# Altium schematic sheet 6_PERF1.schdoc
size 426 x 302 mm; Symbol: Sheet_A3_Whycan; Device: Sheet_A3; @Project Name: Avaota A1 八核 AIoT 开发板; @Update Date: 2024-04-03; @Page No: 8; @Page Count: 13
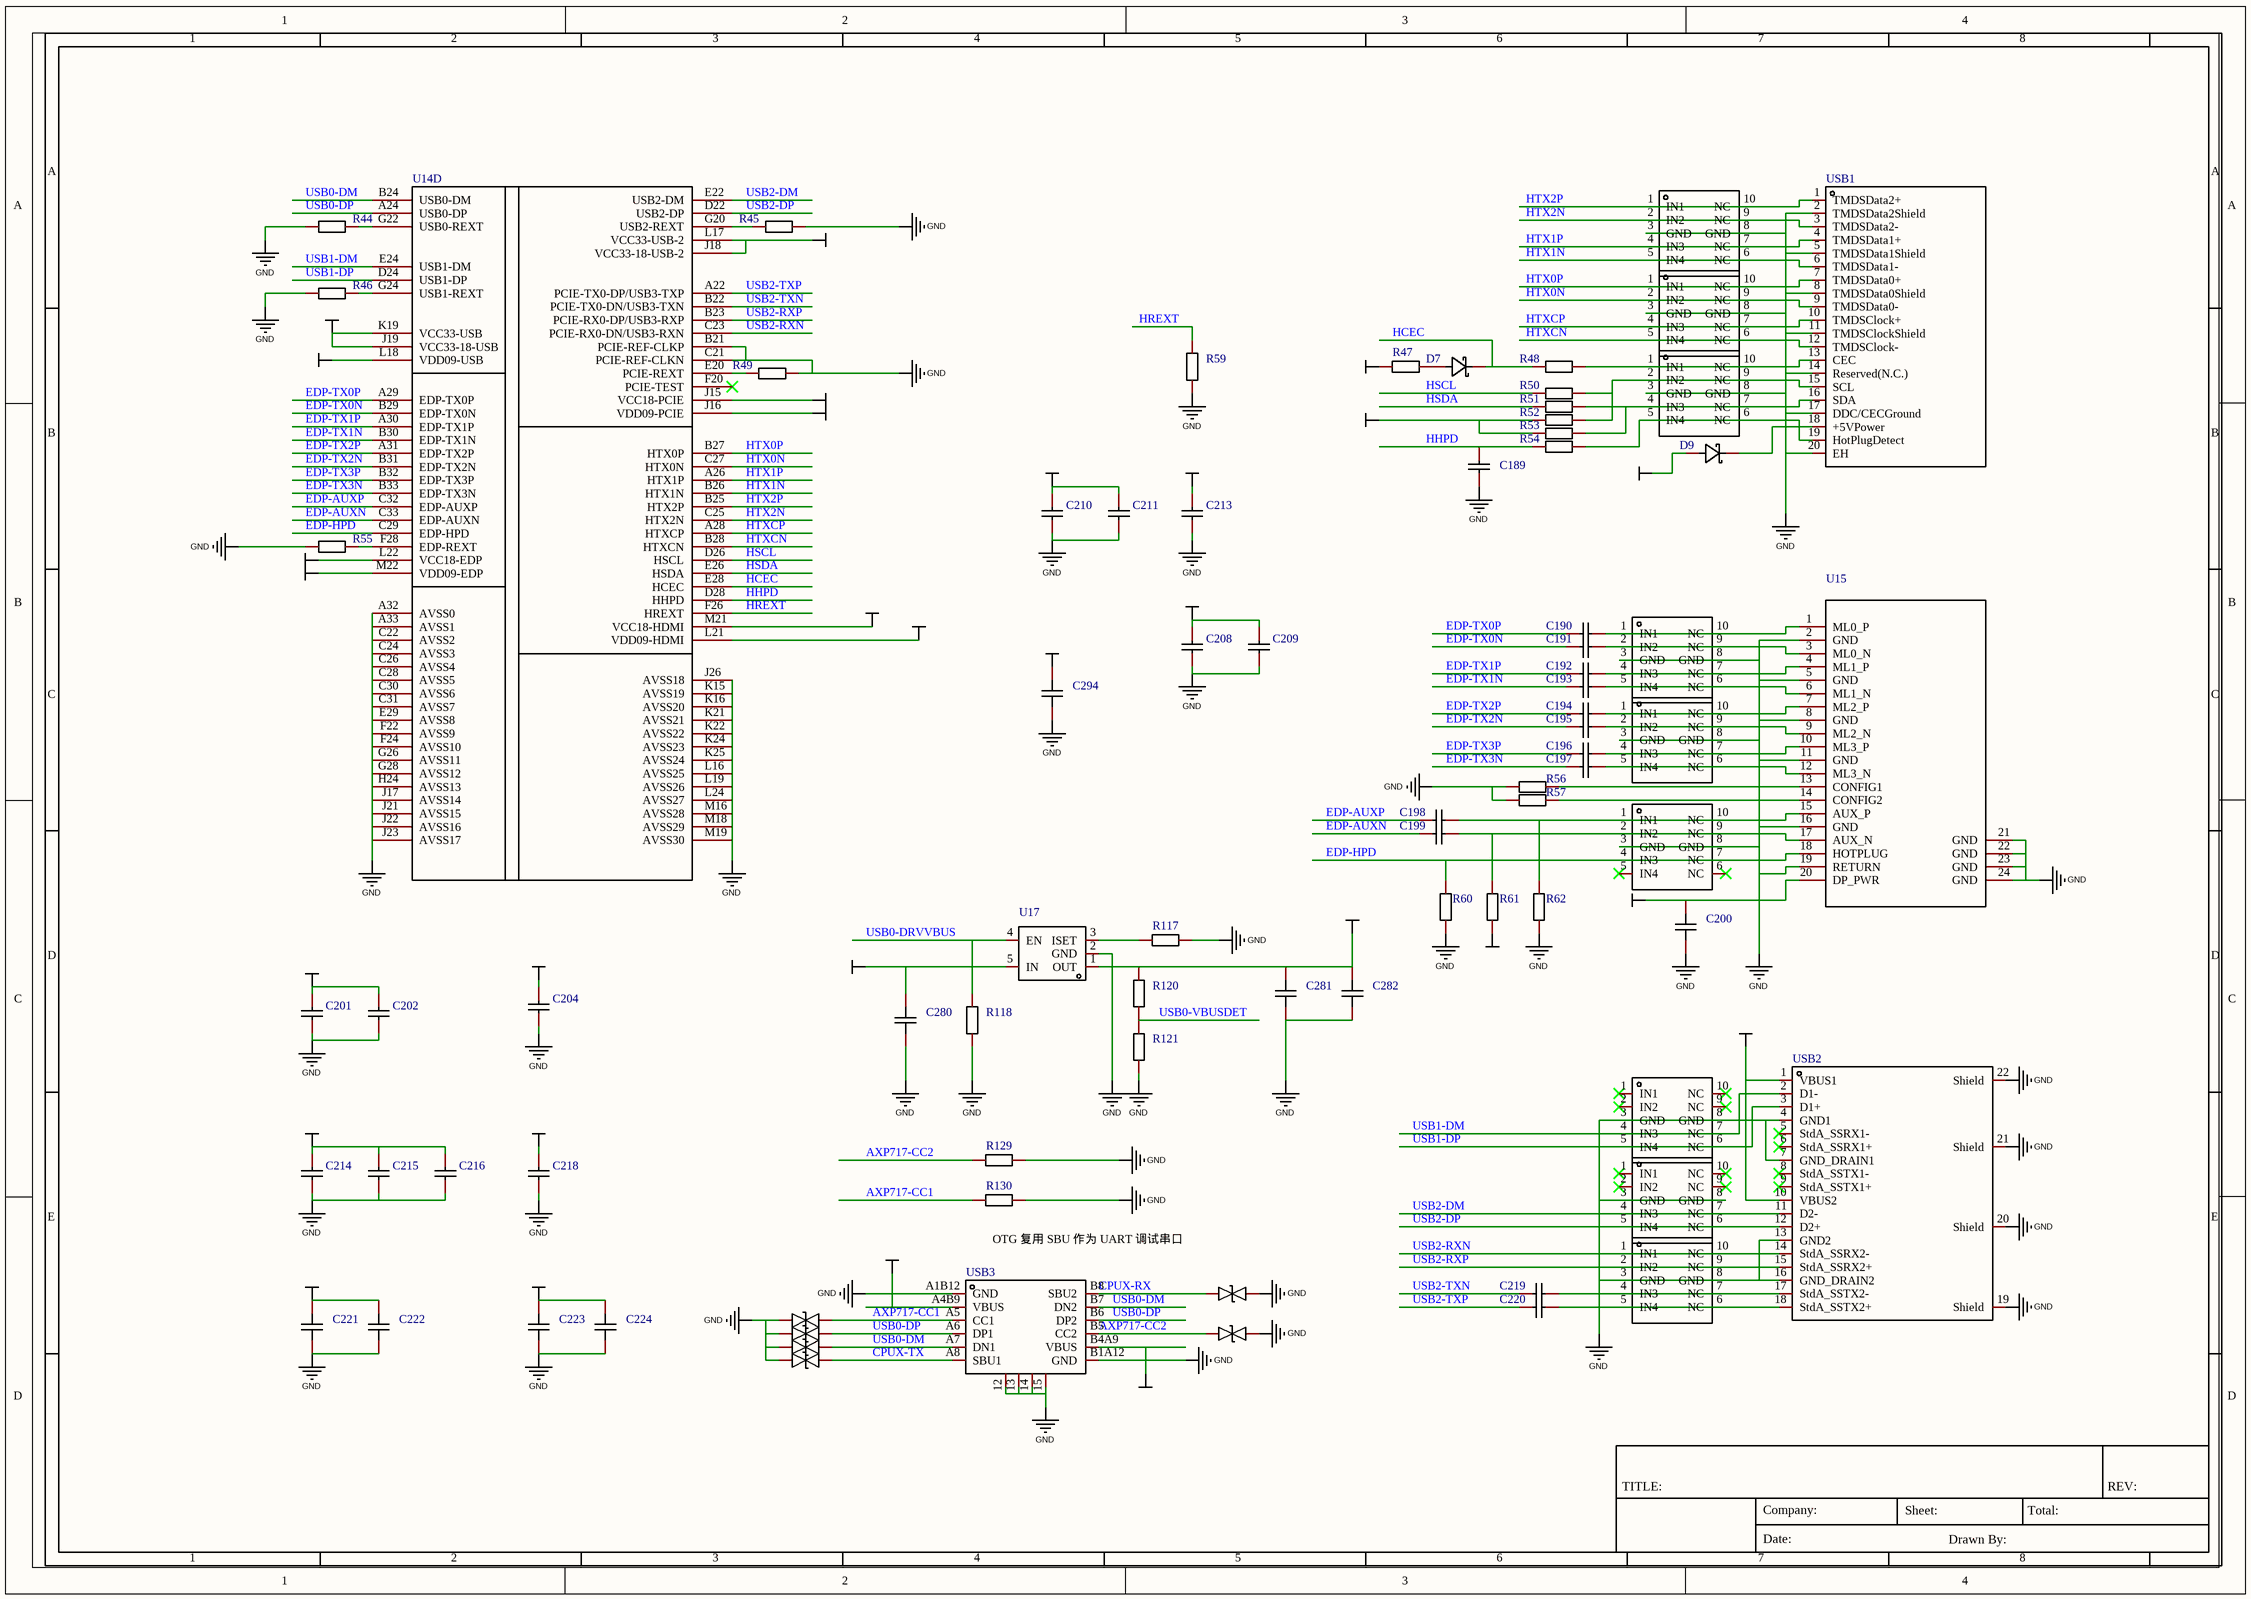
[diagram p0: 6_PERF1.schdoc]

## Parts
C189  GRM033R61A104KE15D  [c0201 nsk]  (value not drawn)
C190  GRM033R61A104KE15D  [c0201 nsk]  (value not drawn)
C191  GRM033R61A104KE15D  [c0201 nsk]  (value not drawn)
C192  GRM033R61A104KE15D  [c0201 nsk]  (value not drawn)
C193  GRM033R61A104KE15D  [c0201 nsk]  (value not drawn)
C194  GRM033R61A104KE15D  [c0201 nsk]  (value not drawn)
C195  GRM033R61A104KE15D  [c0201 nsk]  (value not drawn)
C196  GRM033R61A104KE15D  [c0201 nsk]  (value not drawn)
C197  GRM033R61A104KE15D  [c0201 nsk]  (value not drawn)
C198  GRM033R61A104KE15D  [c0201 nsk]  (value not drawn)
C199  GRM033R61A104KE15D  [c0201 nsk]  (value not drawn)
C200  CAP_0402  [c0402-nsk]  (value not drawn)
C201  GRM033R61A104KE15D  [c0201 nsk]  (value not drawn)
C202  GRM033R61A104KE15D  [c0201 nsk]  (value not drawn)
C204  GRM033R61A104KE15D  [c0201 nsk]  (value not drawn)
C208  GRM033R61A104KE15D  [c0201 nsk]  (value not drawn)
C209  GRM033R61A104KE15D  [c0201 nsk]  (value not drawn)
C210  GRM033R61A104KE15D  [c0201 nsk]  (value not drawn)
C211  GRM033R61A104KE15D  [c0201 nsk]  (value not drawn)
C213  GRM033R61A104KE15D  [c0201 nsk]  (value not drawn)
C214  GRM033R61A104KE15D  [c0201 nsk]  (value not drawn)
C215  GRM033R61A104KE15D  [c0201 nsk]  (value not drawn)
C216  GRM033R61A104KE15D  [c0201 nsk]  (value not drawn)
C218  GRM033R61A104KE15D  [c0201 nsk]  (value not drawn)
C219  GRM033R61A104KE15D  [c0201 nsk]  (value not drawn)
C220  GRM033R61A104KE15D  [c0201 nsk]  (value not drawn)
C221  CAP_0402  [c0402-nsk]  (value not drawn)
C222  CAP_0402  [c0402-nsk]  (value not drawn)
C223  CAP_0402  [c0402-nsk]  (value not drawn)
C224  CAP_0402  [c0402-nsk]  (value not drawn)
C280  CAP_0402  [c0402-nsk]  (value not drawn)
C281  CAP_0603  [C0603-NSK]  (value not drawn)
C282  CAP_0603  [C0603-NSK]  (value not drawn)
C294  CAP_1206  [C1206]  (value not drawn)
D5  RClamp0524PATCT_C40960  [SLP2510P8_L2.5-W1.0-P0.50-BL]  (value not drawn)
D6  RClamp0524PATCT_C40960  [SLP2510P8_L2.5-W1.0-P0.50-BL]  (value not drawn)
D7  B5819WT_C2997265  [SOD-523_L1.2-W0.8-LS1.6-RD-1 NSK]  (value not drawn)
D8  RClamp0524PATCT_C40960  [SLP2510P8_L2.5-W1.0-P0.50-BL]  (value not drawn)
D9  B5819WT_C2997265  [SOD-523_L1.2-W0.8-LS1.6-RD-1 NSK]  (value not drawn)
D10  RClamp0524PATCT_C40960  [SLP2510P8_L2.5-W1.0-P0.50-BL]  (value not drawn)
D11  RClamp0524PATCT_C40960  [SLP2510P8_L2.5-W1.0-P0.50-BL]  (value not drawn)
D12  RClamp0524PATCT_C40960  [SLP2510P8_L2.5-W1.0-P0.50-BL]  (value not drawn)
D13  RClamp0524PATCT_C40960  [SLP2510P8_L2.5-W1.0-P0.50-BL]  (value not drawn)
D14  RClamp0524PATCT_C40960  [SLP2510P8_L2.5-W1.0-P0.50-BL]  (value not drawn)
D15  RClamp0524PATCT_C40960  [SLP2510P8_L2.5-W1.0-P0.50-BL]  (value not drawn)
D24  0402ESDA-05N  [d0402]  (value not drawn)
D25  0402ESDA-05N  [d0402]  (value not drawn)
D26  0402ESDA-05N  [d0402]  (value not drawn)
D27  0402ESDA-05N  [d0402]  (value not drawn)
D30  0402ESDA-05N  [d0402]  (value not drawn)
D31  0402ESDA-05N  [d0402]  (value not drawn)
R44  Res_0201  [r0201 nsk]  (value not drawn)
R45  Res_0201  [r0201 nsk]  (value not drawn)
R46  Res_0201  [r0201 nsk]  (value not drawn)
R47  Res_0201  [r0201 nsk]  (value not drawn)
R48  Res_0201  [r0201 nsk]  (value not drawn)
R49  Res_0201  [r0201 nsk]  (value not drawn)
R50  Res_0201  [r0201 nsk]  (value not drawn)
R51  Res_0201  [r0201 nsk]  (value not drawn)
R52  Res_0201  [r0201 nsk]  (value not drawn)
R53  Res_0201  [r0201 nsk]  (value not drawn)
R54  Res_0201  [r0201 nsk]  (value not drawn)
R55  Res_0201  [r0201 nsk]  (value not drawn)
R56  Res_0201  [r0201 nsk]  (value not drawn)
R57  Res_0201  [r0201 nsk]  (value not drawn)
R59  Res_0201  [r0201 nsk]  (value not drawn)
R60  Res_0201  [r0201 nsk]  (value not drawn)
R61  Res_0201  [r0201 nsk]  (value not drawn)
R62  Res_0201  [r0201 nsk]  (value not drawn)
R117  Res_0201  [r0201 nsk]  (value not drawn)
R118  Res_0201  [r0201 nsk]  (value not drawn)
R120  Res_0201  [r0201 nsk]  (value not drawn)
R121  Res_0201  [r0201 nsk]  (value not drawn)
R129  Res_0201  [r0201 nsk]  (value not drawn)
R130  Res_0201  [r0201 nsk]  (value not drawn)
U14  T527  [T527-BGA664]  (value not drawn)  (part D of 8)
U15  DP_TH_SIDE_VERTICAL  [DP_TH_SIDE_VERTICAL]  (value not drawn)
U17  SY6280AAC_C55136  [SOT-23-5_L3.0-W1.7-P0.95-LS2.8-BL]  (value not drawn)
USB1  HDMI-001C_C2836126  [HDMI-SMD_HDMI-001C]  (value not drawn)
USB2  USB-303WSD-BRY  [USB-A-TH_XUNPU_USB-303WSD-BRY]  (value not drawn)
USB3  TYPEC-304-BCP16  [USB-C-SMD_TYPEC-304-BCP16-1]  (value not drawn)

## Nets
GND: C189.1 C200.1 C201.1 C202.1 C204.1 C208.1 C209.1 C210.1 C211.1 C213.1 C214.1 C215.1 C216.1 C218.1 C221.1 C222.1 C223.1 C224.1 C280.1 C281.1 C282.1 C294.1 D5.3(GND) D5.8(GND) D6.3(GND) D6.8(GND) D8.3(GND) D8.8(GND) D10.3(GND) D10.8(GND) D11.3(GND) D11.8(GND) D12.3(GND) D12.8(GND) D13.3(GND) D13.8(GND) D14.3(GND) D14.8(GND) D15.3(GND) D15.8(GND) D24.1 D25.1 D26.1 D27.1 D30.1 D31.1 R44.1 R45.2 R46.1 R49.1 R55.1 R56.1 R57.1 R59.1 R60.1 R62.1 R117.2 R118.1 R121.1 R129.1 R130.1 U14.A32(AVSS0) U14.A33(AVSS1) U14.B21(PCIE-REF-CLKP) U14.C21(PCIE-REF-CLKN) U14.C22(AVSS2) U14.C24(AVSS3) U14.C26(AVSS4) U14.C28(AVSS5) U14.C30(AVSS6) U14.C31(AVSS7) U14.E29(AVSS8) U14.F22(AVSS9) U14.F24(AVSS10) U14.G26(AVSS11) U14.G28(AVSS12) U14.H24(AVSS13) U14.J17(AVSS14) U14.J21(AVSS15) U14.J22(AVSS16) U14.J23(AVSS17) U14.J26(AVSS18) U14.K15(AVSS19) U14.K16(AVSS20) U14.K21(AVSS21) U14.K22(AVSS22) U14.K24(AVSS23) U14.K25(AVSS24) U14.L16(AVSS25) U14.L19(AVSS26) U14.L24(AVSS27) U14.M16(AVSS28) U14.M18(AVSS29) U14.M19(AVSS30) U15.2(GND) U15.5(GND) U15.8(GND) U15.11(GND) U15.16(GND) U15.19(RETURN) U15.21(GND) U15.22(GND) U15.23(GND) U15.24(GND) U17.2(GND) USB1.2(TMDSData2Shield) USB1.5(TMDSData1Shield) USB1.8(TMDSData0Shield) USB1.11(TMDSClockShield) USB1.14(Reserved(N.C.)) USB1.17(DDC/CECGround) USB1.20(EH) USB2.4(GND1) USB2.7(GND_DRAIN1) USB2.13(GND2) USB2.16(GND_DRAIN2) USB2.19(Shield) USB2.20(Shield) USB2.21(Shield) USB2.22(Shield) USB3.12 USB3.13 USB3.14 USB3.15 USB3.A1B12(GND) USB3.B1A12(GND)
VBUS: C221.2 C222.2 C280.2 C294.2 D9.2(A) R52.1 R53.1 U17.5(IN) USB2.1(VBUS1) USB2.10(VBUS2)
VBUS-USB: C281.2 C282.2 R120.2 U17.1(OUT) USB3.A4B9(VBUS) USB3.B4A9(VBUS)
VCC18-EDP: U14.L22(VCC18-EDP)
VCC18-HDMI: C201.2 C202.2 U14.M21(VCC18-HDMI)
VCC18-PCIE: C208.2 C209.2 U14.J15(VCC18-PCIE)
VCC33-USB: C204.2 U14.J18(VCC33-18-USB-2) U14.J19(VCC33-18-USB) U14.K19(VCC33-USB) U14.L17(VCC33-USB-2)
VCC-3V3: C200.2 C223.2 C224.2 R61.1 U15.20(DP_PWR)
VCC-IO: R47.1
VDD09-EDP: C213.2 U14.M22(VDD09-EDP)
VDD09-HDMI: C214.2 C215.2 C216.2 U14.L21(VDD09-HDMI)
VDD09-PCIE: C210.2 C211.2 U14.J16(VDD09-PCIE)
VDD09-USB: C218.2 U14.L18(VDD09-USB)
AXP717-CC1: D24.2 R130.2 USB3.A5(CC1)
AXP717-CC2: D31.2 R129.2 USB3.B5(CC2)
CPUX-RX: D30.2 USB3.B8(SBU2)
CPUX-TX: D27.2 USB3.A8(SBU1)
EDP-AUXN: C199.1 U14.C33(EDP-AUXN)
EDP-AUXP: C198.1 U14.C32(EDP-AUXP)
EDP-HPD: D12.4(IN3) D12.7(NC) R60.2 U14.C29(EDP-HPD) U15.18(HOTPLUG)
EDP-TX0N: C191.1 U14.B29(EDP-TX0N)
EDP-TX0P: C190.1 U14.A29(EDP-TX0P)
EDP-TX1N: C193.1 U14.B30(EDP-TX1N)
EDP-TX1P: C192.1 U14.A30(EDP-TX1P)
EDP-TX2N: C195.1 U14.B31(EDP-TX2N)
EDP-TX2P: C194.1 U14.A31(EDP-TX2P)
EDP-TX3N: C197.1 U14.B33(EDP-TX3N)
EDP-TX3P: C196.1 U14.B32(EDP-TX3P)
HCEC: D7.1(K) R48.1 U14.E28(HCEC)
HHPD: C189.2 R54.1 U14.D28(HHPD)
HREXT: R59.2 U14.F26(HREXT)
HSCL: R50.1 U14.D26(HSCL)
HSDA: R51.1 U14.E26(HSDA)
HTX0N: D6.2(IN2) D6.9(NC) U14.C27(HTX0N) USB1.9(TMDSData0-)
HTX0P: D6.1(IN1) D6.10(NC) U14.B27(HTX0P) USB1.7(TMDSData0+)
HTX1N: D5.5(IN4) D5.6(NC) U14.B26(HTX1N) USB1.6(TMDSData1-)
HTX1P: D5.4(IN3) D5.7(NC) U14.A26(HTX1P) USB1.4(TMDSData1+)
HTX2N: D5.2(IN2) D5.9(NC) U14.C25(HTX2N) USB1.3(TMDSData2-)
HTX2P: D5.1(IN1) D5.10(NC) U14.B25(HTX2P) USB1.1(TMDSData2+)
HTXCN: D6.5(IN4) D6.6(NC) U14.B28(HTXCN) USB1.12(TMDSClock-)
HTXCP: D6.4(IN3) D6.7(NC) U14.A28(HTXCP) USB1.10(TMDSClock+)
USB0-DM: D26.2 U14.B24(USB0-DM) USB3.A7(DN1) USB3.B7(DN2)
USB0-DP: D25.2 U14.A24(USB0-DP) USB3.A6(DP1) USB3.B6(DP2)
USB0-DRVVBUS: R118.2 U17.4(EN)
USB0-VBUSDET: R120.1 R121.2
USB1-DM: D13.4(IN3) D13.7(NC) U14.E24(USB1-DM) USB2.2(D1-)
USB1-DP: D13.5(IN4) D13.6(NC) U14.D24(USB1-DP) USB2.3(D1+)
USB2-DM: D14.4(IN3) D14.7(NC) U14.E22(USB2-DM) USB2.11(D2-)
USB2-DP: D14.5(IN4) D14.6(NC) U14.D22(USB2-DP) USB2.12(D2+)
USB2-RXN: D15.1(IN1) D15.10(NC) U14.C23(PCIE-RX0-DN/USB3-RXN) USB2.14(StdA_SSRX2-)
USB2-RXP: D15.2(IN2) D15.9(NC) U14.B23(PCIE-RX0-DP/USB3-RXP) USB2.15(StdA_SSRX2+)
USB2-TXN: C219.1 U14.B22(PCIE-TX0-DN/USB3-TXN)
USB2-TXP: C220.1 U14.A22(PCIE-TX0-DP/USB3-TXP)
NetC190_2: C190.2 D10.1(IN1) D10.10(NC) U15.1(ML0_P)
NetC191_2: C191.2 D10.2(IN2) D10.9(NC) U15.3(ML0_N)
NetC192_2: C192.2 D10.4(IN3) D10.7(NC) U15.4(ML1_P)
NetC193_2: C193.2 D10.5(IN4) D10.6(NC) U15.6(ML1_N)
NetC194_2: C194.2 D11.1(IN1) D11.10(NC) U15.7(ML2_P)
NetC195_2: C195.2 D11.2(IN2) D11.9(NC) U15.9(ML2_N)
NetC196_2: C196.2 D11.4(IN3) D11.7(NC) U15.10(ML3_P)
NetC197_2: C197.2 D11.5(IN4) D11.6(NC) U15.12(ML3_N)
NetC198_2: C198.2 D12.1(IN1) D12.10(NC) R62.2 U15.15(AUX_P)
NetC199_2: C199.2 D12.2(IN2) D12.9(NC) R61.2 U15.17(AUX_N)
NetC219_2: C219.2 D15.4(IN3) D15.7(NC) USB2.17(StdA_SSTX2-)
NetC220_2: C220.2 D15.5(IN4) D15.6(NC) USB2.18(StdA_SSTX2+)
NetD7_2: D7.2(A) R47.2
NetD8_1: D8.1(IN1) D8.10(NC) R48.2 USB1.13(CEC)
NetD8_2: D8.2(IN2) D8.9(NC) R50.2 R52.2 USB1.15(SCL)
NetD8_4: D8.4(IN3) D8.7(NC) R51.2 R53.2 USB1.16(SDA)
NetD8_5: D8.5(IN4) D8.6(NC) R54.2 USB1.19(HotPlugDetect)
NetD9_1: D9.1(K) USB1.18(+5VPower)
NetR44_2: R44.2 U14.G22(USB0-REXT)
NetR45_1: R45.1 U14.G20(USB2-REXT)
NetR46_2: R46.2 U14.G24(USB1-REXT)
NetR49_2: R49.2 U14.E20(PCIE-REXT)
NetR55_2: R55.2 U14.F28(EDP-REXT)
NetR56_2: R56.2 U15.13(CONFIG1)
NetR57_2: R57.2 U15.14(CONFIG2)
NetR117_1: R117.1 U17.3(ISET)

Not connected (* = marked no-connect by the designer): D12 5(IN4)* 6(NC)*; D13 1(IN1)* 2(IN2)* 9(NC)* 10(NC)*; D14 1(IN1)* 2(IN2)* 9(NC)* 10(NC)*; U14 F20(PCIE-TEST)*; USB2 5(StdA_SSRX1-)* 6(StdA_SSRX1+)* 8(StdA_SSTX1-)* 9(StdA_SSTX1+)*

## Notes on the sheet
- OTG 复用 SBU 作为 UART 调试串口

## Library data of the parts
C189-C199 C209 C211 C213 C216 C218-C220 = GRM033R61A104KE15D: Manufacturer: muRata(村田); Value: 100nF; Add into BOM: yes; Tolerance: ±10%; Voltage Rated: 10V; Temperature Coefficient: X5R; Description: 容值:100nF;精度:±10%;额定电压:10V;材质(温度系数):X5R;
C200 = CAP_0402: Symbol: CapAcitance; Convert to PCB: yes; Value: 10uF
C201 C202 C204 C208 C210 C214 C215 = GRM033R61A104KE15D: Manufacturer: muRata(村田); Value: 2.2uF; Add into BOM: yes; Tolerance: ±10%; Voltage Rated: 10V; Temperature Coefficient: X5R; Description: 容值:100nF;精度:±10%;额定电压:10V;材质(温度系数):X5R;
C221 C223 = CAP_0402: Symbol: CapAcitance; Convert to PCB: yes; Value: 2.2uF
C222 C224 C280 = CAP_0402: Symbol: CapAcitance; Convert to PCB: yes; Value: 100nF
C281 C282 = CAP_0603: Symbol: CapAcitance; Convert to PCB: yes; Value: 22uF
C294 = CAP_1206: Symbol: CapAcitance; Convert to PCB: yes; Value: 22uF
D5 D6 D8 D10-D15 = RClamp0524PATCT_C40960: Manufacturer: SEMTECH; Add into BOM: yes; Reverse Stand-Off Voltage (Vrwm): 5V; Maximum Clamping Voltage: 15V; Peak Pulse Power Dissipation (Ppp)@10/1000us: 150W; Breakdown Voltage: 6V; Number of Lines: 四路; Type: ESD; Description: 反向截止电压(Vrwm):5V;最大钳位电压:15V;峰值脉冲功率(Ppp)@10/1000us:150W;击穿电压:6V;
D7 D9 = B5819WT_C2997265: Manufacturer: BORN(伯恩半导体); Add into BOM: yes; Forward Voltage (Vf@If): 600mV@200mA; Reverse Voltage (Vr): 40V; Average Rectified Current (Io): 1A; Reverse Leakage Current (Ir): 5uA@30V; Description: 二极管配置:-;正向压降(Vf):600mV@200mA;直流反向耐压(Vr):40V;平均整流电流(Io):1A;
D24-D27 D30 D31 = 0402ESDA-05N: 极性:Bidirectional;反向关断电压（典型值）:5V;击穿电压（最小值）:-;箝位电压:50V;峰值脉冲电流（10/1000us）:-;; Manufacturer: BORN伯恩半导体; Add into BOM: yes; Reverse Stand-Off Voltage (Vrwm): 5V; Clamping Voltage@Ipp: 50V
R44-R46 = Res_0201: Symbol: 电阻; Convert to PCB: yes; Value: 200
R47 R60 = Res_0201: Symbol: 电阻; Convert to PCB: yes; Value: 10K
R48 R50 R51 = Res_0201: Symbol: 电阻; Convert to PCB: yes; Value: 100
R49 R54 R55 R59 = Res_0201: Symbol: 电阻; Convert to PCB: yes; Value: 1K
R52 R53 = Res_0201: Symbol: 电阻; Convert to PCB: yes; Value: 4K7
R56 R57 = Res_0201: Symbol: 电阻; Convert to PCB: yes; Value: 1M
R61 R62 = Res_0201: Symbol: 电阻; Convert to PCB: yes; Value: NC
R117 = Res_0201: Symbol: 电阻; Convert to PCB: yes; Value: 6K8
R118 R121 = Res_0201: Symbol: 电阻; Convert to PCB: yes; Value: 100K
R120 = Res_0201: Symbol: 电阻; Convert to PCB: yes; Value: 180K
R129 R130 = Res_0201: Symbol: 电阻; Convert to PCB: yes; Value: 5.1K
U14 = T527: Add into BOM: yes; SWAP_INFO: (S1+S2+S3+S4+S5+S6+S7+S8+S9); SPLIT_INST: TRUE; Description: Allwinner T527 SoC
U15 = DP_TH_SIDE_VERTICAL: Add into BOM: yes
U17 = SY6280AAC_C55136: Manufacturer: silergy(矽力杰); Add into BOM: yes; Description: 低能耗配电开关
USB1 = HDMI-001C_C2836126: Manufacturer: XUNPU(讯普); Add into BOM: yes; Connector Type: HDMI; Gender: 母; Current Rating (Max): 500mA; Description: 连接器类型:HDMI;公母:母;总PIN位数:19P;安装方式:弯插;排数:2;额定电流:500mA;触头材质:-;触头镀层:-;工作温度范围:-45℃~+85℃;
USB2 = USB-303WSD-BRY: Manufacturer: XUNPU(讯普); Add into BOM: yes; Connector Type: Type-A; Gender: 母; Number of Ports: 2; Number of Contacts: 9P+9P; Current Rating - Power (Max): 1.8A; Soldering Temperature(Max): 260℃; Description: 连接器类型:Type-A;标准:USB 3.0;公母:母;端口数量:2;触点数量:9P+9P;安装方式:弯插;额定电流 - 电源:1.8A;工作温度范围:-30℃~+85℃;焊接温度(最大值):260℃;
USB3 = TYPEC-304-BCP16: Manufacturer: XUNPU; Pin Type: IN; Add into BOM: yes; Check: false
